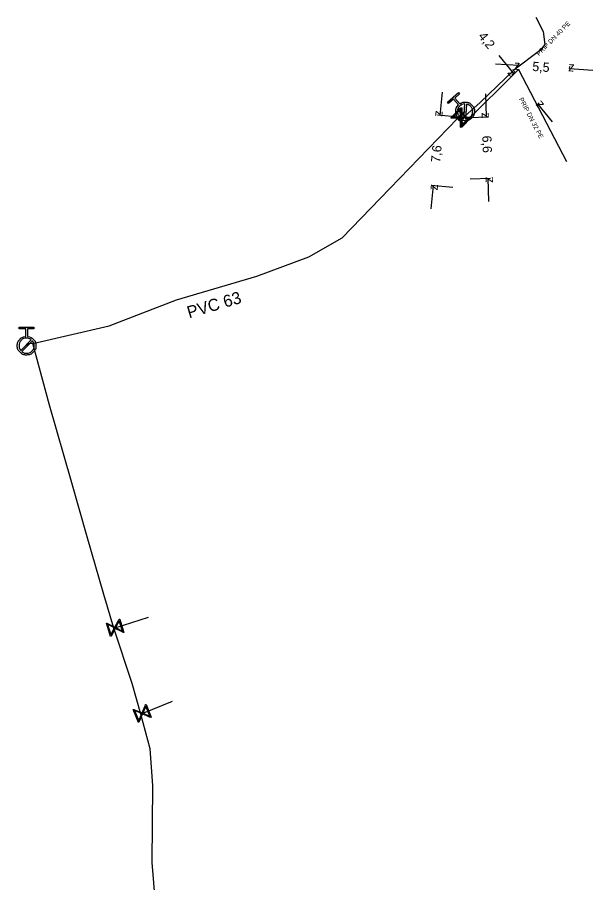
# Model space of a CAD drawing. Extents: x -641905 to -641246, y -1111750 to -1110210.
# Drawn here: x -641553.5 to -641491.5, y -1110303.2 to -1110209.9 of the extents above; entities that cross this region are included whole.
import ezdxf

# ---------------------------------------------------------------- set-up
doc = ezdxf.new("R2010")
doc.units = 0
for name, color, linetype in [('Default', 7, 'Continuous'), ('VP Hydrant', 7, 'Continuous'), ('VP Kótování', 7, 'Continuous'), ('VP Popis přípojky', 7, 'Continuous'), ('VP Přípojka', 7, 'Continuous'), ('VP Řad', 7, 'Continuous'), ('VP Řad - popis', 7, 'Continuous'), ('VP Šoupě', 7, 'Continuous')]:
    doc.layers.add(name, color=color, linetype=linetype)

msp = doc.modelspace()

# ---------------------------------------------------------------- linework, layer by layer
at = {"layer": 'Default'}
for points in [[(-641505.821, -1110219.241), (-641505.529, -1110219.029), (-641505.164, -1110219.059), (-641504.753, -1110219.092), (-641504.482, -1110219.408), (-641504.213, -1110219.723), (-641504.245, -1110220.135), (-641504.278, -1110220.547), (-641504.594, -1110220.818), (-641504.907, -1110221.086), (-641505.32, -1110221.055), (-641505.732, -1110221.023), (-641506.001, -1110220.709), (-641506.272, -1110220.393), (-641506.241, -1110219.981), (-641506.216, -1110219.615), (-641505.961, -1110219.36)], [(-641505.271, -1110219.243), (-641505.552, -1110219.249), (-641505.774, -1110219.44), (-641506.031, -1110219.659), (-641506.057, -1110219.994), (-641506.083, -1110220.329), (-641505.863, -1110220.585), (-641505.672, -1110220.808), (-641505.396, -1110220.857)], [(-641505.215, -1110220.871), (-641504.937, -1110220.862), (-641504.717, -1110220.674), (-641504.462, -1110220.455), (-641504.435, -1110220.12), (-641504.409, -1110219.785), (-641504.629, -1110219.528), (-641504.817, -1110219.309), (-641505.09, -1110219.257)], [(-641552.444, -1110244.311), (-641552.085, -1110244.339), (-641551.826, -1110244.598), (-641551.534, -1110244.89), (-641551.533, -1110245.306), (-641551.532, -1110245.72), (-641551.824, -1110246.013), (-641552.116, -1110246.306), (-641552.532, -1110246.307), (-641552.944, -1110246.308), (-641553.238, -1110246.017), (-641553.532, -1110245.726), (-641553.533, -1110245.312), (-641553.534, -1110244.896), (-641553.244, -1110244.602), (-641552.987, -1110244.339), (-641552.628, -1110244.311)], [(-641552.027, -1110244.669), (-641552.244, -1110244.492), (-641552.537, -1110244.492), (-641552.875, -1110244.493), (-641553.112, -1110244.731), (-641553.349, -1110244.969), (-641553.348, -1110245.307), (-641553.347, -1110245.6), (-641553.168, -1110245.816)], [(-641553.039, -1110245.945), (-641552.822, -1110246.118), (-641552.533, -1110246.117), (-641552.197, -1110246.116), (-641551.959, -1110245.879), (-641551.722, -1110245.641), (-641551.723, -1110245.303), (-641551.723, -1110245.014), (-641551.898, -1110244.797)]]:
    msp.add_open_spline(points, degree=3, dxfattribs=at)
at = {"layer": 'VP Hydrant'}
for points in [[(-641505.961, -1110219.36), (-641506.494, -1110218.737), (-641507.018, -1110219.185), (-641507.137, -1110219.046), (-641505.95, -1110218.03), (-641505.831, -1110218.169), (-641506.355, -1110218.618), (-641505.821, -1110219.241)], [(-641505.396, -1110220.857), (-641505.271, -1110219.243)], [(-641505.09, -1110219.257), (-641505.215, -1110220.871)], [(-641552.628, -1110244.311), (-641552.63, -1110243.491), (-641553.319, -1110243.493), (-641553.32, -1110243.309), (-641551.757, -1110243.305), (-641551.757, -1110243.488), (-641552.446, -1110243.49), (-641552.444, -1110244.311)], [(-641553.168, -1110245.816), (-641552.027, -1110244.669)], [(-641551.898, -1110244.797), (-641553.039, -1110245.945)]]:
    msp.add_lwpolyline(points, dxfattribs=at)
at = {"layer": 'VP Kótování'}
for points in [[(-641501.593, -1110214.029), (-641500.023, -1110215.975)], [(-641501.959, -1110214.913), (-641499.465, -1110215.085)], [(-641499.462, -1110215.052), (-641499.447, -1110214.835)], [(-641491.484, -1110215.636), (-641493.978, -1110215.464)], [(-641493.976, -1110215.431), (-641493.961, -1110215.214)], [(-641499.886, -1110215.865), (-641500.218, -1110216.132)], [(-641507.729, -1110217.992), (-641507.962, -1110220.481)], [(-641503.028, -1110218.153), (-641502.955, -1110220.652)], [(-641497.249, -1110219.134), (-641497.581, -1110219.401)], [(-641495.816, -1110221.19), (-641497.386, -1110219.244)], [(-641505.872, -1110220.676), (-641508.211, -1110220.458)], [(-641504.874, -1110220.708), (-641502.705, -1110220.644)], [(-641504.68, -1110227.305), (-641502.511, -1110227.241)], [(-641502.687, -1110229.748), (-641502.761, -1110227.249)], [(-641506.578, -1110228.244), (-641508.917, -1110228.025)], [(-641508.9, -1110230.538), (-641508.668, -1110228.049)]]:
    msp.add_lwpolyline(points, dxfattribs=at)
at = {"layer": 'VP Přípojka'}
for points in [[(-641497.601, -1110209.909), (-641496.83, -1110211.43), (-641496.63, -1110212.85), (-641497.06, -1110213.4), (-641499.99, -1110215.62), (-641503.63, -1110219.075), (-641505.6, -1110220.86), (-641505.708, -1110220.728), (-641505.836, -1110220.576)], [(-641506.07, -1110220.82), (-641505.961, -1110220.95), (-641505.347, -1110221.361), (-641499.497, -1110215.551), (-641494.324, -1110225.464)], [(-641505.836, -1110220.576), (-641505.53, -1110220.25), (-641505.25, -1110220.05)], [(-641551.87, -1110245.05), (-641552.24, -1110245.11), (-641552.54, -1110245.3)], [(-641543.12, -1110275.75), (-641543.055, -1110275.73), (-641542.99, -1110275.71), (-641539.392, -1110274.574)], [(-641540.21, -1110285.02), (-641540.06, -1110284.94), (-641536.782, -1110283.607)]]:
    msp.add_lwpolyline(points, dxfattribs=at)
at = {"layer": 'VP Řad'}
msp.add_lwpolyline([(-641538.45, -1110307.59), (-641539, -1110300.99), (-641538.92, -1110292.7), (-641539.22, -1110288.75), (-641540.21, -1110285.02), (-641541.13, -1110281.72), (-641543.12, -1110275.75), (-641544.22, -1110272.12), (-641545.989, -1110265.89), (-641547.71, -1110259.83), (-641550.07, -1110251.72), (-641551.87, -1110245.05), (-641543.63, -1110243.16), (-641536.38, -1110240.37), (-641527.71, -1110237.8), (-641522.1, -1110235.72), (-641518.5, -1110233.67), (-641513.35, -1110228.36), (-641506.07, -1110220.82), (-641505.836, -1110220.576)], dxfattribs=at)
at = {"layer": 'VP Šoupě'}
for points in [[(-641504.647, -1110220.709), (-641505.689, -1110221.789), (-641505.736, -1110221.743), (-641505.734, -1110221.615), (-641505.75, -1110220.775), (-641506.721, -1110220.793), (-641506.768, -1110220.747), (-641505.727, -1110219.668), (-641505.679, -1110219.714), (-641505.664, -1110220.685), (-641504.824, -1110220.669), (-641504.695, -1110220.664), (-641504.647, -1110220.709)], [(-641504.566, -1110220.682), (-641505.608, -1110221.762), (-641505.655, -1110221.716), (-641505.653, -1110221.588), (-641505.669, -1110220.748), (-641506.64, -1110220.766), (-641506.687, -1110220.72), (-641505.645, -1110219.641), (-641505.598, -1110219.687), (-641505.583, -1110220.658), (-641504.743, -1110220.642), (-641504.613, -1110220.637), (-641504.566, -1110220.682)], [(-641506.595, -1110220.703), (-641505.752, -1110220.687), (-641505.768, -1110219.846), (-641506.595, -1110220.703)], [(-641506.514, -1110220.676), (-641505.671, -1110220.66), (-641505.687, -1110219.819), (-641506.514, -1110220.676)], [(-641505.001, -1110220.876), (-641506.08, -1110219.835), (-641506.015, -1110219.768), (-641504.936, -1110220.809), (-641505.001, -1110220.876)], [(-641504.824, -1110220.758), (-641505.662, -1110220.773), (-641505.646, -1110221.61), (-641504.824, -1110220.758)], [(-641504.743, -1110220.731), (-641505.581, -1110220.746), (-641505.565, -1110221.583), (-641504.743, -1110220.731)], [(-641542.494, -1110274.773), (-641542.053, -1110276.206), (-641542.116, -1110276.226), (-641542.228, -1110276.162), (-641542.971, -1110275.77), (-641543.424, -1110276.628), (-641543.487, -1110276.648), (-641543.928, -1110275.214), (-641543.865, -1110275.195), (-641543.007, -1110275.651), (-641542.615, -1110274.908), (-641542.557, -1110274.792), (-641542.494, -1110274.773)], [(-641543.442, -1110276.474), (-641543.048, -1110275.729), (-641543.792, -1110275.336), (-641543.442, -1110276.474)], [(-641542.537, -1110274.951), (-641542.929, -1110275.692), (-641542.189, -1110276.083), (-641542.537, -1110274.951)], [(-641539.647, -1110283.963), (-641539.082, -1110285.353), (-641539.143, -1110285.378), (-641539.26, -1110285.324), (-641540.034, -1110284.998), (-641540.411, -1110285.893), (-641540.472, -1110285.918), (-641541.037, -1110284.528), (-641540.976, -1110284.503), (-641540.081, -1110284.883), (-641539.756, -1110284.109), (-641539.708, -1110283.988), (-641539.647, -1110283.963)], [(-641540.442, -1110285.741), (-641540.116, -1110284.964), (-641540.891, -1110284.638), (-641540.442, -1110285.741)], [(-641539.675, -1110284.144), (-641540, -1110284.917), (-641539.229, -1110285.241), (-641539.675, -1110284.144)]]:
    msp.add_lwpolyline(points, dxfattribs=at)

# ---------------------------------------------------------------- texts
at = {"layer": 'VP Kótování'}
for s, rotation, p in [('4,2', 308.89086, (-641503.888, -1110211.98)), ('z', 356.04823, (-641499.998, -1110215.549)), ('5,5', 356.04823, (-641498.023, -1110215.686)), ('z', 308.89086, (-641500.726, -1110215.9)), ('z', 176.04823, (-641493.445, -1110215)), ('z', 128.89086, (-641496.683, -1110219.32)), ('z', 264.67052, (-641508.413, -1110219.937)), ('z', 271.68517, (-641503.469, -1110220.167)), ('6,6', 271.68517, (-641503.395, -1110222.674)), ('7,6', 84.67052, (-641507.937, -1110225.597)), ('z', 91.68517, (-641502.246, -1110227.734)), ('z', 84.67052, (-641508.216, -1110228.593))]:
    msp.add_text(s, height=1, rotation=rotation, dxfattribs=at).set_placement(p)
at = {"layer": 'VP Popis přípojky'}
for s, rotation, p in [('PRIP DN 40 PE', 45.53471, (-641497.271, -1110214.106)), ('PRIP DN 32 PE', 297.55809, (-641499.459, -1110218.718))]:
    msp.add_text(s, height=0.5, rotation=rotation, dxfattribs=at).set_placement(p)
at = {"layer": 'VP Řad - popis'}
msp.add_text('PVC 63', height=1.3, rotation=16.5111, dxfattribs=at).set_placement((-641535.005, -1110242.369))

doc.saveas('drawing.dxf')
